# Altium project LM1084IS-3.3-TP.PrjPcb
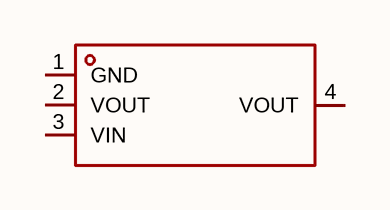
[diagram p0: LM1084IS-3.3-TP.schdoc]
1 sheet, 1 parts. Net scope: global (net labels, ports and power ports of the same name join across sheets).

## Sheet LM1084IS-3.3-TP.schdoc
size 127 x 101 mm

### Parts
U?  lm1084is-3.3-tp  [TO-263-3L_L10.2-W8.9-P2.54-LS15.6-BL]  (value not drawn)

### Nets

Not connected (* = marked no-connect by the designer): U? 1(GND) 2(VOUT) 3(VIN) 4(VOUT)

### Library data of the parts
U? = lm1084is-3.3-tp: 输出极性:正极;工作电压:12V;输出电压:3.3V;输出电流:5A;电源纹波抑制比(PSRR):72dB@(120Hz);输出类型:固定;; Manufacturer: TECH PUBLIC(台舟); AddInBom: yes; ModelId: 685f1e9000f443d08a0cee8120ed2ed5; ModelTransform: 401.574,614.172,0,0,0,0,0,45.709,0; Output Configuration: 正极; Voltage - Supply: 12V; Output Voltage: 3.3V; Output Current: 5A; Voltage Dropout: 1.5V; Noise: 0.003%Vout; Output Type: 固定; Number of Outputs: 1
